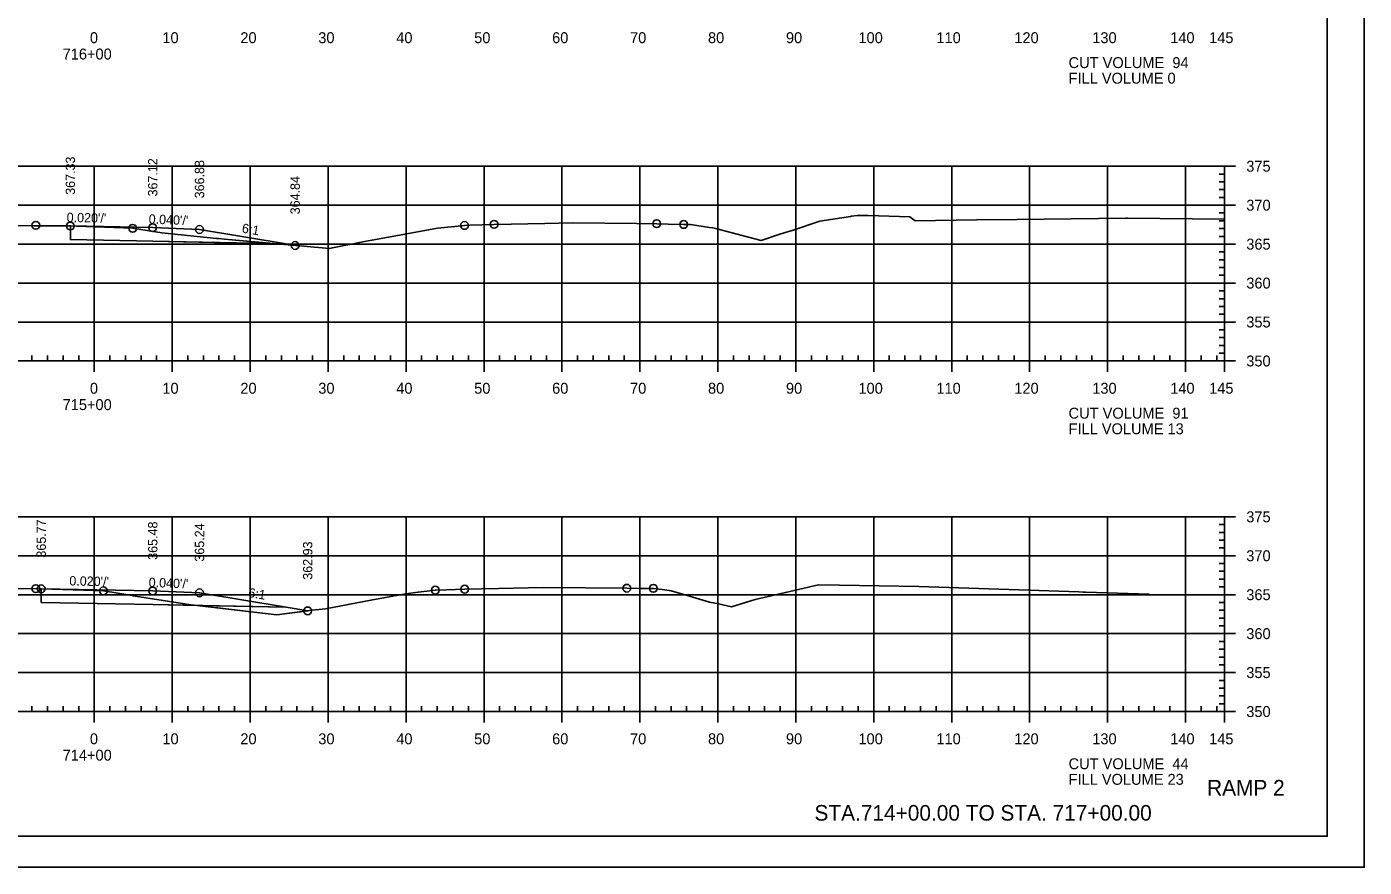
# Model space of a CAD drawing. Extents: x 1359801 to 1362404, y 372415 to 374228.
# Drawn here: x 1360578.9 to 1360750.5, y 373588 to 373695.8 of the extents above; entities that cross this region are included whole.
import ezdxf

# ---------------------------------------------------------------- set-up
doc = ezdxf.new("R2010")
doc.units = 0
for name, color, linetype in [('S_DRG_PT_SYM', 7, 'Continuous'), ('S_ELECTRIC_UTILITIES_ANNOT', 7, 'Continuous'), ('S_IRON_PIN', 7, 'Continuous'), ('S_MAILBOX', 7, 'Continuous'), ('S_PRIMARY_CTL', 7, 'Continuous'), ('S_SANITARY_SEWER', 7, 'Continuous'), ('S_SHOULDER', 7, 'Continuous'), ('S_SIGN', 7, 'Continuous'), ('S_UNDERGROUND_CABLE', 7, 'Continuous'), ('S_UTL_PT_SYM', 7, 'Continuous'), ('S_WATER_UTILITIES', 7, 'Continuous')]:
    doc.layers.add(name, color=color, linetype=linetype)

msp = doc.modelspace()

# ---------------------------------------------------------------- linework, layer by layer
at = {"layer": 'S_DRG_PT_SYM'}
for points in [[(1360558.12, 373670.48), (1360579.87, 373670.31), (1360584.46, 373670.27), (1360585.25, 373670.24), (1360592.46, 373669.97), (1360592.7, 373669.93), (1360596.2, 373669.39), (1360603.19, 373668.68), (1360603.53, 373668.65), (1360604.25, 373668.58), (1360611.05, 373667.97), (1360617.72, 373667.38), (1360617.89, 373667.41), (1360622, 373668.25), (1360628.33, 373669.4), (1360631.55, 373669.97), (1360633.77, 373670.2), (1360635.03, 373670.34), (1360635.71, 373670.36), (1360638.83, 373670.48), (1360645.32, 373670.6), (1360648.93, 373670.66), (1360657.11, 373670.58), (1360659.69, 373670.56), (1360661.15, 373670.52), (1360663.14, 373670.47), (1360664.02, 373670.44), (1360666.46, 373670.09), (1360666.89, 373670.03), (1360667.58, 373669.88), (1360673.07, 373668.4), (1360675.37, 373669.19), (1360676.15, 373669.44), (1360677.06, 373669.7), (1360680.61, 373670.89), (1360684.55, 373671.5), (1360684.67, 373671.53), (1360685.4, 373671.63), (1360686.82, 373671.61), (1360692.16, 373671.46), (1360692.35, 373671.32), (1360692.84, 373670.95), (1360700.72, 373671.08), (1360705.87, 373671.1), (1360719.89, 373671.27), (1360720.03, 373671.27), (1360720.09, 373671.27), (1360732.53, 373671.13)], [(1360573.32, 373623.79), (1360580.72, 373623.7), (1360586.17, 373623.53), (1360588.71, 373623.44), (1360592.39, 373622.82), (1360592.52, 373622.8), (1360592.76, 373622.76), (1360599.96, 373621.66), (1360607.67, 373620.72), (1360610.96, 373620.37), (1360615.49, 373620.94), (1360617.19, 373621.12), (1360623.03, 373622.22), (1360627.45, 373623.06), (1360628.75, 373623.22), (1360631.28, 373623.52), (1360632.67, 373623.57), (1360635.05, 373623.65), (1360639.37, 373623.74), (1360645.13, 373623.85), (1360650.54, 373623.81), (1360655.86, 373623.77), (1360657.43, 373623.75), (1360659.26, 373623.75), (1360660.73, 373623.55), (1360661.55, 373623.43), (1360663.45, 373622.88), (1360666.46, 373622), (1360667.63, 373621.75), (1360669.27, 373621.39), (1360671.77, 373622.17), (1360672.33, 373622.34), (1360676.21, 373623.23), (1360680.43, 373624.19), (1360683.14, 373624.16), (1360693.31, 373623.99), (1360713.86, 373623.29), (1360714.39, 373623.27), (1360714.48, 373623.27), (1360714.74, 373623.27), (1360722.85, 373623.01)]]:
    msp.add_lwpolyline(points, dxfattribs=at)
at = {"layer": 'S_ELECTRIC_UTILITIES_ANNOT'}
for p, q in [((1360610.84, 373667.99), (1360604.25, 373668.58)), ((1360612.14, 373667.97), (1360610.84, 373667.99)), ((1360610.84, 373667.99), (1360611.05, 373667.97)), ((1360611.05, 373667.97), (1360613.3, 373667.77)), ((1360613.3, 373667.77), (1360612.14, 373667.97)), ((1360580.72, 373623.7), (1360580.72, 373621.95)), ((1360600.86, 373621.55), (1360599.96, 373621.66)), ((1360612.14, 373621.32), (1360600.86, 373621.55)), ((1360600.86, 373621.55), (1360607.67, 373620.72)), ((1360614.91, 373620.86), (1360612.14, 373621.32))]:
    msp.add_line(p, q, dxfattribs=at)
for points in [[(1360604.25, 373668.58), (1360603.53, 373668.65), (1360603.19, 373668.68), (1360596.2, 373669.39), (1360592.7, 373669.93), (1360592.46, 373669.97), (1360585.25, 373670.24), (1360584.46, 373670.27)], [(1360584.46, 373670.27), (1360584.46, 373668.52), (1360595.03, 373668.31), (1360610.84, 373667.99)], [(1360599.96, 373621.66), (1360592.76, 373622.76), (1360592.52, 373622.8), (1360592.39, 373622.82), (1360588.71, 373623.44), (1360586.17, 373623.53), (1360580.72, 373623.7)], [(1360580.72, 373621.95), (1360595.03, 373621.67), (1360600.86, 373621.55)], [(1360607.67, 373620.72), (1360610.96, 373620.37), (1360614.91, 373620.86)]]:
    msp.add_lwpolyline(points, dxfattribs=at)
at = {"layer": 'S_MAILBOX'}
for p, q in [((1360442.53, 373677.94), (1360732.53, 373677.94)), ((1360587.53, 373652.94), (1360587.53, 373677.94)), ((1360597.53, 373652.94), (1360597.53, 373677.94)), ((1360607.53, 373652.94), (1360607.53, 373677.94)), ((1360617.53, 373652.94), (1360617.53, 373677.94)), ((1360627.53, 373652.94), (1360627.53, 373677.94)), ((1360637.53, 373652.94), (1360637.53, 373677.94)), ((1360647.53, 373652.94), (1360647.53, 373677.94)), ((1360657.53, 373652.94), (1360657.53, 373677.94)), ((1360667.53, 373652.94), (1360667.53, 373677.94)), ((1360677.53, 373652.94), (1360677.53, 373677.94)), ((1360687.53, 373652.94), (1360687.53, 373677.94)), ((1360697.53, 373652.94), (1360697.53, 373677.94)), ((1360707.53, 373652.94), (1360707.53, 373677.94)), ((1360717.53, 373652.94), (1360717.53, 373677.94)), ((1360727.53, 373652.94), (1360727.53, 373677.94)), ((1360732.53, 373652.94), (1360732.53, 373677.94)), ((1360442.53, 373672.94), (1360732.53, 373672.94)), ((1360442.53, 373667.94), (1360732.53, 373667.94)), ((1360442.53, 373662.94), (1360732.53, 373662.94)), ((1360442.53, 373657.94), (1360732.53, 373657.94)), ((1360442.53, 373652.94), (1360732.53, 373652.94)), ((1360442.53, 373632.94), (1360732.53, 373632.94)), ((1360587.53, 373607.94), (1360587.53, 373632.94)), ((1360597.53, 373607.94), (1360597.53, 373632.94)), ((1360607.53, 373607.94), (1360607.53, 373632.94)), ((1360617.53, 373607.94), (1360617.53, 373632.94)), ((1360627.53, 373607.94), (1360627.53, 373632.94)), ((1360637.53, 373607.94), (1360637.53, 373632.94)), ((1360647.53, 373607.94), (1360647.53, 373632.94)), ((1360657.53, 373607.94), (1360657.53, 373632.94)), ((1360667.53, 373607.94), (1360667.53, 373632.94)), ((1360677.53, 373607.94), (1360677.53, 373632.94)), ((1360687.53, 373607.94), (1360687.53, 373632.94)), ((1360697.53, 373607.94), (1360697.53, 373632.94)), ((1360707.53, 373607.94), (1360707.53, 373632.94)), ((1360717.53, 373607.94), (1360717.53, 373632.94)), ((1360727.53, 373607.94), (1360727.53, 373632.94)), ((1360732.53, 373607.94), (1360732.53, 373632.94)), ((1360442.53, 373627.94), (1360732.53, 373627.94)), ((1360442.53, 373622.94), (1360732.53, 373622.94)), ((1360442.53, 373617.94), (1360732.53, 373617.94)), ((1360442.53, 373612.94), (1360732.53, 373612.94)), ((1360442.53, 373607.94), (1360732.53, 373607.94))]:
    msp.add_line(p, q, dxfattribs=at)
at = {"layer": 'S_SANITARY_SEWER'}
for points in [[(1360584.46, 373670.27), (1360595.03, 373670.06), (1360601.03, 373669.82), (1360612.14, 373667.97), (1360613.3, 373667.77)], [(1360580.72, 373623.7), (1360595.03, 373623.42), (1360601.03, 373623.18), (1360612.14, 373621.32), (1360614.91, 373620.86)]]:
    msp.add_lwpolyline(points, dxfattribs=at)
at = {"layer": 'S_SHOULDER'}
msp.add_line((1360417.13, 373587.96), (1360750.46, 373587.96), dxfattribs=at)
for points in [[(1360417.12, 373801.29), (1360750.46, 373801.29), (1360750.46, 373587.95), (1360417.12, 373587.95)], [(1360663.45, 373797.4), (1360663.45, 373787.52), (1360699.18, 373787.52), (1360699.18, 373784.6), (1360722.38, 373784.6), (1360722.38, 373760.26), (1360745.71, 373760.26), (1360745.71, 373591.94), (1360429.53, 373591.94), (1360429.53, 373797.4)]]:
    msp.add_lwpolyline(points, close=True, dxfattribs=at)
for centre in [(1360659.69, 373670.56), (1360580.03, 373670.36), (1360584.46, 373670.27), (1360592.46, 373669.97), (1360595.03, 373670.06), (1360601.03, 373669.82), (1360635.03, 373670.34), (1360638.83, 373670.48), (1360663.14, 373670.47), (1360613.3, 373667.77), (1360580.03, 373623.72), (1360580.72, 373623.7), (1360588.71, 373623.44), (1360595.03, 373623.42), (1360601.03, 373623.18), (1360631.28, 373623.52), (1360635.05, 373623.65), (1360655.86, 373623.77), (1360659.26, 373623.75), (1360614.91, 373620.86)]:
    msp.add_circle(centre, 0.5, dxfattribs=at)
at = {"layer": 'S_UNDERGROUND_CABLE'}
for points in [[(1360584.46, 373670.27), (1360584.46, 373668.52), (1360584.46, 373668.52), (1360595.03, 373668.31), (1360612.14, 373667.97)], [(1360580.72, 373623.7), (1360580.72, 373621.95)], [(1360580.72, 373621.95), (1360595.03, 373621.67), (1360612.14, 373621.32)]]:
    msp.add_lwpolyline(points, dxfattribs=at)
at = {"layer": 'S_UTL_PT_SYM'}
for q in [(1360745.71, 373797.4), (1360429.53, 373591.94)]:
    msp.add_line((1360745.71, 373591.94), q, dxfattribs=at)
at = {"layer": 'S_WATER_UTILITIES'}
for p, q in [((1360732.53, 373652.94), (1360732.53, 373677.94)), ((1360733.93, 373677.94), (1360732.53, 373677.94)), ((1360732.53, 373676.94), (1360731.83, 373676.94)), ((1360732.53, 373675.94), (1360731.83, 373675.94)), ((1360732.53, 373674.94), (1360731.83, 373674.94)), ((1360732.53, 373673.94), (1360731.83, 373673.94)), ((1360733.93, 373672.94), (1360732.53, 373672.94)), ((1360732.53, 373671.94), (1360731.83, 373671.94)), ((1360732.53, 373670.94), (1360731.83, 373670.94)), ((1360732.53, 373669.94), (1360731.83, 373669.94)), ((1360732.53, 373668.94), (1360731.83, 373668.94)), ((1360733.93, 373667.94), (1360732.53, 373667.94)), ((1360732.53, 373666.94), (1360731.83, 373666.94)), ((1360732.53, 373665.94), (1360731.83, 373665.94)), ((1360732.53, 373664.94), (1360731.83, 373664.94)), ((1360732.53, 373663.94), (1360731.83, 373663.94)), ((1360733.93, 373662.94), (1360732.53, 373662.94)), ((1360732.53, 373661.94), (1360731.83, 373661.94)), ((1360732.53, 373660.94), (1360731.83, 373660.94)), ((1360732.53, 373659.94), (1360731.83, 373659.94)), ((1360732.53, 373658.94), (1360731.83, 373658.94)), ((1360733.93, 373657.94), (1360732.53, 373657.94)), ((1360732.53, 373656.94), (1360731.83, 373656.94)), ((1360732.53, 373655.94), (1360731.83, 373655.94)), ((1360732.53, 373654.94), (1360731.83, 373654.94)), ((1360732.53, 373653.94), (1360731.83, 373653.94)), ((1360442.53, 373652.94), (1360732.53, 373652.94)), ((1360579.53, 373652.94), (1360579.53, 373653.64)), ((1360581.53, 373652.94), (1360581.53, 373653.64)), ((1360583.53, 373652.94), (1360583.53, 373653.64)), ((1360585.53, 373652.94), (1360585.53, 373653.64)), ((1360587.53, 373651.54), (1360587.53, 373652.94)), ((1360589.53, 373652.94), (1360589.53, 373653.64)), ((1360591.53, 373652.94), (1360591.53, 373653.64)), ((1360593.53, 373652.94), (1360593.53, 373653.64)), ((1360595.53, 373652.94), (1360595.53, 373653.64)), ((1360597.53, 373651.54), (1360597.53, 373652.94)), ((1360599.53, 373652.94), (1360599.53, 373653.64)), ((1360601.53, 373652.94), (1360601.53, 373653.64)), ((1360603.53, 373652.94), (1360603.53, 373653.64)), ((1360605.53, 373652.94), (1360605.53, 373653.64)), ((1360607.53, 373651.54), (1360607.53, 373652.94)), ((1360609.53, 373652.94), (1360609.53, 373653.64)), ((1360611.53, 373652.94), (1360611.53, 373653.64)), ((1360613.53, 373652.94), (1360613.53, 373653.64)), ((1360615.53, 373652.94), (1360615.53, 373653.64)), ((1360617.53, 373651.54), (1360617.53, 373652.94)), ((1360619.53, 373652.94), (1360619.53, 373653.64)), ((1360621.53, 373652.94), (1360621.53, 373653.64)), ((1360623.53, 373652.94), (1360623.53, 373653.64)), ((1360625.53, 373652.94), (1360625.53, 373653.64)), ((1360627.53, 373651.54), (1360627.53, 373652.94)), ((1360629.53, 373652.94), (1360629.53, 373653.64)), ((1360631.53, 373652.94), (1360631.53, 373653.64)), ((1360633.53, 373652.94), (1360633.53, 373653.64)), ((1360635.53, 373652.94), (1360635.53, 373653.64)), ((1360637.53, 373651.54), (1360637.53, 373652.94)), ((1360639.53, 373652.94), (1360639.53, 373653.64)), ((1360641.53, 373652.94), (1360641.53, 373653.64)), ((1360643.53, 373652.94), (1360643.53, 373653.64)), ((1360645.53, 373652.94), (1360645.53, 373653.64)), ((1360647.53, 373651.54), (1360647.53, 373652.94)), ((1360649.53, 373652.94), (1360649.53, 373653.64)), ((1360651.53, 373652.94), (1360651.53, 373653.64)), ((1360653.53, 373652.94), (1360653.53, 373653.64)), ((1360655.53, 373652.94), (1360655.53, 373653.64)), ((1360657.53, 373651.54), (1360657.53, 373652.94)), ((1360659.53, 373652.94), (1360659.53, 373653.64)), ((1360661.53, 373652.94), (1360661.53, 373653.64)), ((1360663.53, 373652.94), (1360663.53, 373653.64)), ((1360665.53, 373652.94), (1360665.53, 373653.64)), ((1360667.53, 373651.54), (1360667.53, 373652.94)), ((1360669.53, 373652.94), (1360669.53, 373653.64)), ((1360671.53, 373652.94), (1360671.53, 373653.64)), ((1360673.53, 373652.94), (1360673.53, 373653.64)), ((1360675.53, 373652.94), (1360675.53, 373653.64)), ((1360677.53, 373651.54), (1360677.53, 373652.94)), ((1360679.53, 373652.94), (1360679.53, 373653.64)), ((1360681.53, 373652.94), (1360681.53, 373653.64)), ((1360683.53, 373652.94), (1360683.53, 373653.64)), ((1360685.53, 373652.94), (1360685.53, 373653.64)), ((1360687.53, 373651.54), (1360687.53, 373652.94)), ((1360689.53, 373652.94), (1360689.53, 373653.64)), ((1360691.53, 373652.94), (1360691.53, 373653.64)), ((1360693.53, 373652.94), (1360693.53, 373653.64)), ((1360695.53, 373652.94), (1360695.53, 373653.64)), ((1360697.53, 373651.54), (1360697.53, 373652.94)), ((1360699.53, 373652.94), (1360699.53, 373653.64)), ((1360701.53, 373652.94), (1360701.53, 373653.64)), ((1360703.53, 373652.94), (1360703.53, 373653.64)), ((1360705.53, 373652.94), (1360705.53, 373653.64)), ((1360707.53, 373651.54), (1360707.53, 373652.94)), ((1360709.53, 373652.94), (1360709.53, 373653.64)), ((1360711.53, 373652.94), (1360711.53, 373653.64)), ((1360713.53, 373652.94), (1360713.53, 373653.64)), ((1360715.53, 373652.94), (1360715.53, 373653.64)), ((1360717.53, 373651.54), (1360717.53, 373652.94)), ((1360719.53, 373652.94), (1360719.53, 373653.64)), ((1360721.53, 373652.94), (1360721.53, 373653.64)), ((1360723.53, 373652.94), (1360723.53, 373653.64)), ((1360725.53, 373652.94), (1360725.53, 373653.64)), ((1360727.53, 373651.54), (1360727.53, 373652.94)), ((1360729.53, 373652.94), (1360729.53, 373653.64)), ((1360731.53, 373652.94), (1360731.53, 373653.64)), ((1360732.53, 373651.54), (1360732.53, 373652.94)), ((1360733.93, 373652.94), (1360732.53, 373652.94)), ((1360732.53, 373631.94), (1360731.83, 373631.94)), ((1360732.53, 373607.94), (1360732.53, 373632.94)), ((1360733.93, 373632.94), (1360732.53, 373632.94)), ((1360732.53, 373630.94), (1360731.83, 373630.94)), ((1360732.53, 373629.94), (1360731.83, 373629.94)), ((1360732.53, 373628.94), (1360731.83, 373628.94)), ((1360732.53, 373626.94), (1360731.83, 373626.94)), ((1360733.93, 373627.94), (1360732.53, 373627.94)), ((1360732.53, 373625.94), (1360731.83, 373625.94)), ((1360732.53, 373624.94), (1360731.83, 373624.94)), ((1360732.53, 373623.94), (1360731.83, 373623.94)), ((1360732.53, 373621.94), (1360731.83, 373621.94)), ((1360733.93, 373622.94), (1360732.53, 373622.94)), ((1360732.53, 373620.94), (1360731.83, 373620.94)), ((1360732.53, 373619.94), (1360731.83, 373619.94)), ((1360732.53, 373618.94), (1360731.83, 373618.94)), ((1360733.93, 373617.94), (1360732.53, 373617.94)), ((1360732.53, 373616.94), (1360731.83, 373616.94)), ((1360732.53, 373615.94), (1360731.83, 373615.94)), ((1360732.53, 373614.94), (1360731.83, 373614.94)), ((1360732.53, 373613.94), (1360731.83, 373613.94)), ((1360733.93, 373612.94), (1360732.53, 373612.94)), ((1360732.53, 373611.94), (1360731.83, 373611.94)), ((1360732.53, 373610.94), (1360731.83, 373610.94)), ((1360732.53, 373609.94), (1360731.83, 373609.94)), ((1360442.53, 373607.94), (1360732.53, 373607.94)), ((1360579.53, 373607.94), (1360579.53, 373608.64)), ((1360581.53, 373607.94), (1360581.53, 373608.64)), ((1360583.53, 373607.94), (1360583.53, 373608.64)), ((1360585.53, 373607.94), (1360585.53, 373608.64)), ((1360587.53, 373606.54), (1360587.53, 373607.94)), ((1360589.53, 373607.94), (1360589.53, 373608.64)), ((1360591.53, 373607.94), (1360591.53, 373608.64)), ((1360593.53, 373607.94), (1360593.53, 373608.64)), ((1360595.53, 373607.94), (1360595.53, 373608.64)), ((1360597.53, 373606.54), (1360597.53, 373607.94)), ((1360599.53, 373607.94), (1360599.53, 373608.64)), ((1360601.53, 373607.94), (1360601.53, 373608.64)), ((1360603.53, 373607.94), (1360603.53, 373608.64)), ((1360605.53, 373607.94), (1360605.53, 373608.64)), ((1360607.53, 373606.54), (1360607.53, 373607.94)), ((1360609.53, 373607.94), (1360609.53, 373608.64)), ((1360611.53, 373607.94), (1360611.53, 373608.64)), ((1360613.53, 373607.94), (1360613.53, 373608.64)), ((1360615.53, 373607.94), (1360615.53, 373608.64)), ((1360617.53, 373606.54), (1360617.53, 373607.94)), ((1360619.53, 373607.94), (1360619.53, 373608.64)), ((1360621.53, 373607.94), (1360621.53, 373608.64)), ((1360623.53, 373607.94), (1360623.53, 373608.64)), ((1360625.53, 373607.94), (1360625.53, 373608.64)), ((1360627.53, 373606.54), (1360627.53, 373607.94)), ((1360629.53, 373607.94), (1360629.53, 373608.64)), ((1360631.53, 373607.94), (1360631.53, 373608.64)), ((1360633.53, 373607.94), (1360633.53, 373608.64)), ((1360635.53, 373607.94), (1360635.53, 373608.64)), ((1360637.53, 373606.54), (1360637.53, 373607.94)), ((1360639.53, 373607.94), (1360639.53, 373608.64)), ((1360641.53, 373607.94), (1360641.53, 373608.64)), ((1360643.53, 373607.94), (1360643.53, 373608.64)), ((1360645.53, 373607.94), (1360645.53, 373608.64)), ((1360647.53, 373606.54), (1360647.53, 373607.94)), ((1360649.53, 373607.94), (1360649.53, 373608.64)), ((1360651.53, 373607.94), (1360651.53, 373608.64)), ((1360653.53, 373607.94), (1360653.53, 373608.64)), ((1360655.53, 373607.94), (1360655.53, 373608.64)), ((1360657.53, 373606.54), (1360657.53, 373607.94)), ((1360659.53, 373607.94), (1360659.53, 373608.64)), ((1360661.53, 373607.94), (1360661.53, 373608.64)), ((1360663.53, 373607.94), (1360663.53, 373608.64)), ((1360665.53, 373607.94), (1360665.53, 373608.64)), ((1360667.53, 373606.54), (1360667.53, 373607.94)), ((1360669.53, 373607.94), (1360669.53, 373608.64)), ((1360671.53, 373607.94), (1360671.53, 373608.64)), ((1360673.53, 373607.94), (1360673.53, 373608.64)), ((1360675.53, 373607.94), (1360675.53, 373608.64)), ((1360677.53, 373606.54), (1360677.53, 373607.94)), ((1360679.53, 373607.94), (1360679.53, 373608.64)), ((1360681.53, 373607.94), (1360681.53, 373608.64)), ((1360683.53, 373607.94), (1360683.53, 373608.64)), ((1360685.53, 373607.94), (1360685.53, 373608.64)), ((1360687.53, 373606.54), (1360687.53, 373607.94)), ((1360689.53, 373607.94), (1360689.53, 373608.64)), ((1360691.53, 373607.94), (1360691.53, 373608.64)), ((1360693.53, 373607.94), (1360693.53, 373608.64)), ((1360695.53, 373607.94), (1360695.53, 373608.64)), ((1360697.53, 373606.54), (1360697.53, 373607.94)), ((1360699.53, 373607.94), (1360699.53, 373608.64)), ((1360701.53, 373607.94), (1360701.53, 373608.64)), ((1360703.53, 373607.94), (1360703.53, 373608.64)), ((1360705.53, 373607.94), (1360705.53, 373608.64)), ((1360707.53, 373606.54), (1360707.53, 373607.94)), ((1360709.53, 373607.94), (1360709.53, 373608.64)), ((1360711.53, 373607.94), (1360711.53, 373608.64)), ((1360713.53, 373607.94), (1360713.53, 373608.64)), ((1360715.53, 373607.94), (1360715.53, 373608.64)), ((1360717.53, 373606.54), (1360717.53, 373607.94)), ((1360719.53, 373607.94), (1360719.53, 373608.64)), ((1360721.53, 373607.94), (1360721.53, 373608.64)), ((1360723.53, 373607.94), (1360723.53, 373608.64)), ((1360725.53, 373607.94), (1360725.53, 373608.64)), ((1360727.53, 373606.54), (1360727.53, 373607.94)), ((1360729.53, 373607.94), (1360729.53, 373608.64)), ((1360731.53, 373607.94), (1360731.53, 373608.64)), ((1360732.53, 373608.94), (1360731.83, 373608.94)), ((1360732.53, 373606.54), (1360732.53, 373607.94)), ((1360733.93, 373607.94), (1360732.53, 373607.94))]:
    msp.add_line(p, q, dxfattribs=at)

# ---------------------------------------------------------------- texts
at = {"layer": 'S_IRON_PIN'}
for s, rotation, p in [('367.33', 90, (1360585.06, 373674.27)), ('367.12', 90, (1360595.63, 373674.06)), ('366.88', 90, (1360601.63, 373673.82)), ('364.84', 90, (1360613.9, 373671.77)), ("0.020'/'", 358.8542, (1360583.98, 373670.78)), ("0.040'/'", 357.7094, (1360594.49, 373670.58)), ('6:1', 350.5377, (1360606.4, 373669.43)), ('365.77', 90, (1360581.32, 373627.7)), ('365.48', 90, (1360595.63, 373627.42)), ('365.24', 90, (1360601.63, 373627.18)), ('362.93', 90, (1360615.51, 373624.86)), ("0.020'/'", 358.8542, (1360584.32, 373624.13)), ("0.040'/'", 357.7094, (1360594.49, 373623.94)), ('6:1', 350.5377, (1360607.21, 373622.65))]:
    msp.add_text(s, height=1.2, rotation=rotation, dxfattribs=at).set_placement(p)
at = {"layer": 'S_PRIMARY_CTL'}
for s, p in [('0', (1360586.97, 373693.74)), ('10', (1360596.27, 373693.74)), ('20', (1360606.27, 373693.74)), ('30', (1360616.27, 373693.74)), ('40', (1360626.27, 373693.74)), ('50', (1360636.27, 373693.74)), ('60', (1360646.27, 373693.74)), ('70', (1360656.27, 373693.74)), ('80', (1360666.27, 373693.74)), ('90', (1360676.27, 373693.74)), ('100', (1360685.57, 373693.74)), ('110', (1360695.57, 373693.74)), ('120', (1360705.57, 373693.74)), ('130', (1360715.57, 373693.74)), ('140', (1360725.57, 373693.74)), ('145', (1360730.56, 373693.74)), ('716+00', (1360583.47, 373691.64)), ('CUT VOLUME  94', (1360712.53, 373690.54)), ('FILL VOLUME 0', (1360712.53, 373688.54)), ('375', (1360735.33, 373677.24)), ('370', (1360735.33, 373672.24)), ('365', (1360735.33, 373667.24)), ('360', (1360735.33, 373662.24)), ('355', (1360735.33, 373657.24)), ('350', (1360735.33, 373652.24)), ('0', (1360586.97, 373648.74)), ('10', (1360596.27, 373648.74)), ('20', (1360606.27, 373648.74)), ('30', (1360616.27, 373648.74)), ('40', (1360626.27, 373648.74)), ('50', (1360636.27, 373648.74)), ('60', (1360646.27, 373648.74)), ('70', (1360656.27, 373648.74)), ('80', (1360666.27, 373648.74)), ('90', (1360676.27, 373648.74)), ('100', (1360685.57, 373648.74)), ('110', (1360695.57, 373648.74)), ('120', (1360705.57, 373648.74)), ('130', (1360715.57, 373648.74)), ('140', (1360725.57, 373648.74)), ('145', (1360730.56, 373648.74)), ('715+00', (1360583.47, 373646.64)), ('CUT VOLUME  91', (1360712.53, 373645.54)), ('FILL VOLUME 13', (1360712.53, 373643.54)), ('375', (1360735.33, 373632.24)), ('370', (1360735.33, 373627.24)), ('365', (1360735.33, 373622.24)), ('360', (1360735.33, 373617.24)), ('355', (1360735.33, 373612.24)), ('350', (1360735.33, 373607.24)), ('0', (1360586.97, 373603.74)), ('10', (1360596.27, 373603.74)), ('20', (1360606.27, 373603.74)), ('30', (1360616.27, 373603.74)), ('40', (1360626.27, 373603.74)), ('50', (1360636.27, 373603.74)), ('60', (1360646.27, 373603.74)), ('70', (1360656.27, 373603.74)), ('80', (1360666.27, 373603.74)), ('90', (1360676.27, 373603.74)), ('100', (1360685.57, 373603.74)), ('110', (1360695.57, 373603.74)), ('120', (1360705.57, 373603.74)), ('130', (1360715.57, 373603.74)), ('140', (1360725.57, 373603.74)), ('145', (1360730.56, 373603.74)), ('714+00', (1360583.47, 373601.64)), ('CUT VOLUME  44', (1360712.53, 373600.54)), ('FILL VOLUME 23', (1360712.53, 373598.54))]:
    msp.add_text(s, height=1.4, dxfattribs=at).set_placement(p)
at = {"layer": 'S_SHOULDER'}
for p in [(1360584.41, 373670.22), (1360580.67, 373623.65)]:
    msp.add_text('+', height=0.1, dxfattribs=at).set_placement(p)
at = {"layer": 'S_SIGN'}
for s, p in [('RAMP 2', (1360730.3, 373597.16)), ('STA.714+00.00 TO STA. 717+00.00', (1360679.93, 373593.94))]:
    msp.add_text(s, height=2, dxfattribs=at).set_placement(p)

doc.saveas('drawing.dxf')
